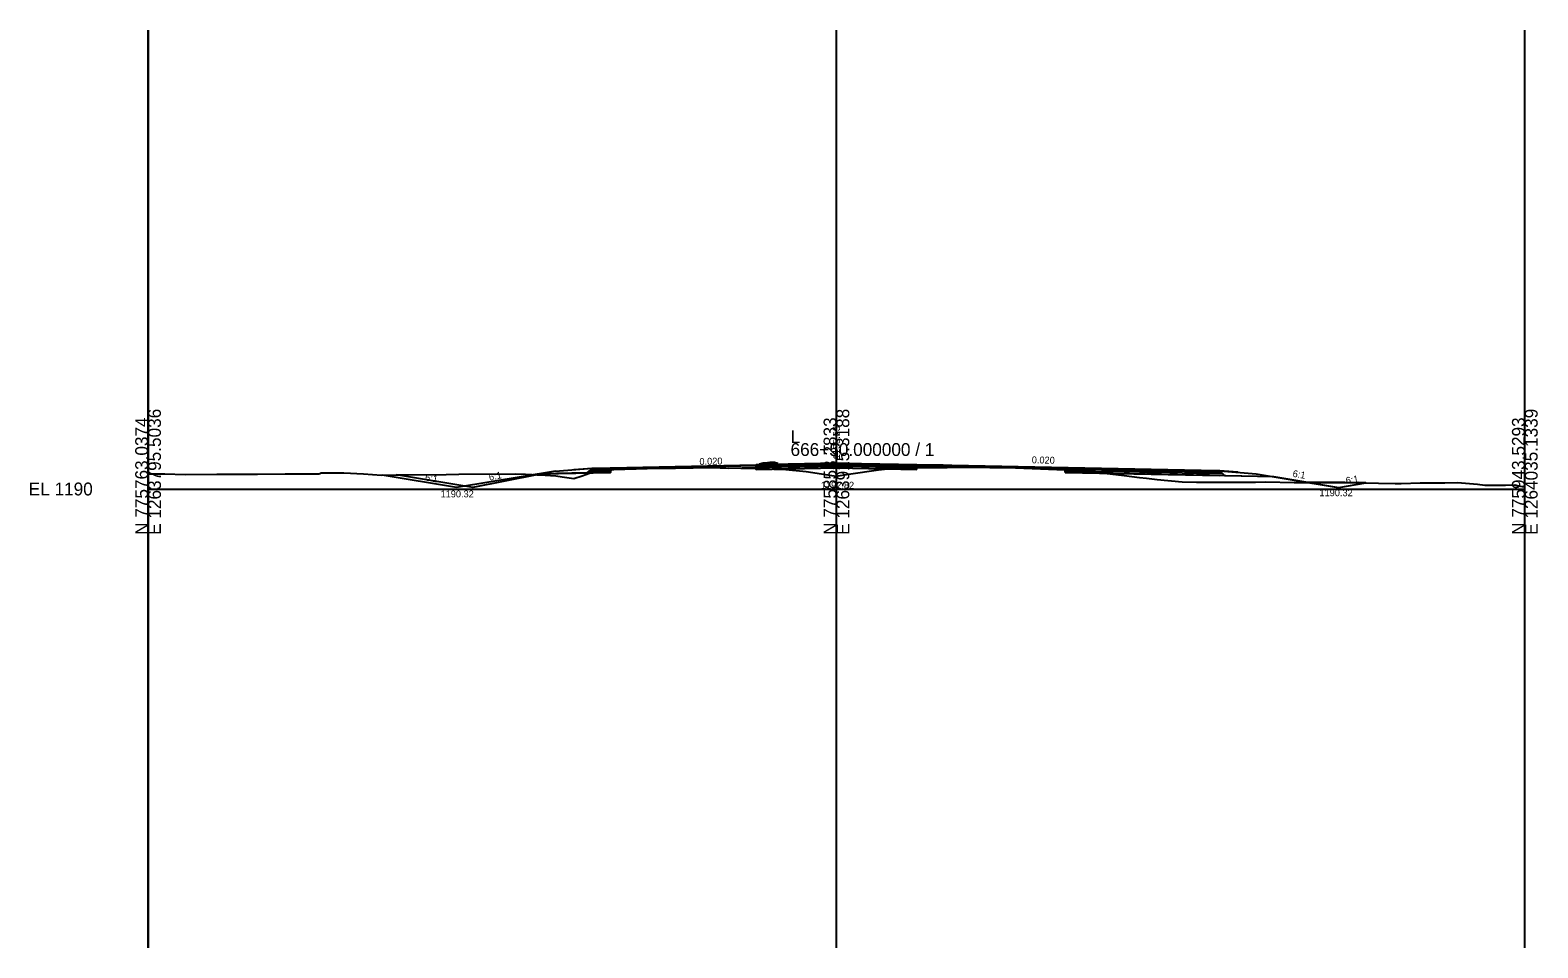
# Model space of a CAD drawing. Extents: x -41 to 1262860, y -100 to 777489.
# Drawn here: x -25.7 to 302.8, y 1805 to 2005 of the extents above; entities that cross this region are included whole.
import ezdxf

# ---------------------------------------------------------------- set-up
doc = ezdxf.new("R2010")
doc.units = 0
for name, color, linetype in [('Exist Cross Section Cell', 7, 'Continuous'), ('Exist XS Center Line Elevation Label', 7, 'Continuous'), ('Exist XS Ground Line', 7, 'Continuous'), ('Prop CMT Pvmt Course 1', 7, 'Continuous'), ('Prop CMT Pvmt Course 2', 7, 'Continuous'), ('Prop CMT Pvmt Course 4', 7, 'Continuous'), ('Prop CMT Pvmt Surface', 7, 'Continuous'), ('Prop CMT Shld Paved Course 1', 7, 'Continuous'), ('Prop CMT Shld Paved Course 2', 7, 'Continuous'), ('Prop CMT Shld Paved Course 4', 7, 'Continuous'), ('Prop CMT Subgrade Earthwork', 7, 'Continuous'), ('Prop Conc Curb and Gutter', 7, 'Continuous'), ('Prop Conc Island Cover', 7, 'Continuous'), ('Prop XS Ditch Standard Text', 7, 'Continuous'), ('Prop XS Earthwork Shape', 7, 'Continuous'), ('Prop XS Exc Vertical Line 1', 7, 'Continuous'), ('Prop XS Exc Vertical Line 2', 7, 'Continuous'), ('Prop XS Exc Vertical Line 3', 7, 'Continuous'), ('Prop XS Finish Grade', 7, 'Continuous'), ('Prop XS Hydro Elevations', 7, 'Continuous'), ('Prop XS SE Text', 7, 'Continuous'), ('Prop XS Side Slope Text', 7, 'Continuous'), ('Scratch_Level_4', 7, 'Continuous'), ('Scratch_Level_5', 7, 'Continuous'), ('Scratch_Level_6', 7, 'Continuous')]:
    doc.layers.add(name, color=color, linetype=linetype)

msp = doc.modelspace()

# ---------------------------------------------------------------- linework, layer by layer
at = {"layer": 'Exist Cross Section Cell'}
for p, q in [((150, 1905), (150, 1915)), ((0, 1905), (150, 1905)), ((150, 1905), (300, 1905))]:
    msp.add_line(p, q, dxfattribs=at)
at = {"layer": 'Exist XS Ground Line'}
msp.add_lwpolyline([(0, 1908.32), (3.62, 1908.27), (8.07, 1908.16), (14.98, 1908.25), (16.8, 1908.26), (23.82, 1908.26), (29.87, 1908.33), (37.24, 1908.31), (37.42, 1908.39), (37.74, 1908.54), (42.69, 1908.5), (46.95, 1908.32), (50.86, 1908.02), (54.64, 1908.12), (64.93, 1908.19), (67.7, 1908.24), (80.12, 1908.28), (82.21, 1908.24), (86.52, 1908.01), (88.89, 1907.85), (90.23, 1907.65), (92.78, 1907.3), (94.6, 1907.88), (96.18, 1908.47), (98, 1908.76), (99.23, 1908.96), (100.09, 1909.06), (101.49, 1909.24), (108.76, 1909.46), (110.72, 1909.52), (114.93, 1909.57), (122.69, 1909.66), (132.39, 1909.44), (135.4, 1909.37), (136.35, 1909.34), (139, 1909.27), (143.39, 1908.79), (145.8, 1908.42), (149.96, 1907.82), (152.65, 1908.23), (159.19, 1909.21), (161.1, 1909.42), (161.43, 1909.44), (164.51, 1909.58), (165.67, 1909.59), (176.58, 1909.75), (177.81, 1909.74), (188.99, 1909.59), (199.82, 1909.19), (201.18, 1909.14), (201.48, 1909.12), (204.78, 1908.94), (206.45, 1908.73), (212.71, 1907.91), (216.01, 1907.51), (217.55, 1907.35), (219.86, 1907.07), (225.33, 1906.54), (228.44, 1906.47), (232.88, 1906.51), (234.56, 1906.5), (241.28, 1906.5), (243.54, 1906.54), (249.75, 1906.45), (256.43, 1906.44), (260.81, 1906.39), (268.11, 1906.26), (271.76, 1906.19), (273.05, 1906.22), (277.23, 1906.32), (282.56, 1906.35), (285.34, 1906.45), (289.66, 1906.08), (291.26, 1905.87), (295.76, 1905.87), (297.84, 1905.9), (298.09, 1905.83), (298.63, 1905.72), (300, 1905.49)], dxfattribs=at)
at = {"layer": 'Prop CMT Pvmt Course 1'}
for points in [[(100.79, 1909.39), (100.79, 1909.64), (132.5, 1910.28), (132.5, 1910.28), (132.5, 1910.03), (132.5, 1910.03), (132.5, 1910.03), (100.79, 1909.39), (100.79, 1909.39)], [(229.45, 1908.79), (229.45, 1909.04), (175.13, 1910.12), (175.13, 1910.12), (174.75, 1910.13), (174.75, 1910.13), (174.1, 1910.14), (174.1, 1910.14), (173.25, 1910.16), (173.25, 1910.16), (172.3, 1910.18), (172.3, 1910.18), (171.37, 1910.2), (171.37, 1910.2), (170.58, 1910.21), (170.58, 1910.21), (170.02, 1910.23), (170.02, 1910.23), (167.5, 1910.28), (167.5, 1910.28), (167.5, 1910.03), (167.5, 1910.03), (167.5, 1910.03), (170.02, 1909.98), (170.02, 1909.98), (170.58, 1909.96), (170.58, 1909.96), (171.37, 1909.95), (171.37, 1909.95), (172.3, 1909.93), (172.3, 1909.93), (173.25, 1909.91), (173.25, 1909.91), (174.1, 1909.89), (174.1, 1909.89), (174.75, 1909.88), (174.75, 1909.88), (175.13, 1909.87), (175.13, 1909.87), (229.45, 1908.79), (229.45, 1908.79)]]:
    msp.add_lwpolyline(points, dxfattribs=at)
at = {"layer": 'Prop CMT Pvmt Course 2'}
msp.add_lwpolyline([(132.5, 1909.69), (138, 1909.8), (150, 1910.05), (150, 1910.05), (155.44, 1909.94), (155.44, 1909.94), (167.5, 1909.69), (167.5, 1909.69), (167.5, 1910.03), (155.44, 1910.27), (155.44, 1910.27), (150, 1910.38), (150, 1910.38), (138, 1910.14), (132.5, 1910.03)], dxfattribs=at)
at = {"layer": 'Prop CMT Pvmt Course 4'}
msp.add_line((132.5, 1909.69), (132.5, 1909.24), dxfattribs=at)
at = {"layer": 'Prop CMT Pvmt Surface'}
for p, q in [((96.78, 1909.56), (100.79, 1909.64)), ((100.79, 1909.64), (132.5, 1910.28)), ((132.5, 1910.28), (150, 1910.63)), ((150, 1910.63), (167.5, 1910.28)), ((167.5, 1910.28), (229.45, 1909.04)), ((229.45, 1909.04), (233.54, 1908.96))]:
    msp.add_line(p, q, dxfattribs=at)
at = {"layer": 'Prop CMT Shld Paved Course 1'}
msp.add_line((100.77, 1909.64), (100.79, 1909.64), dxfattribs=at)
for points in [[(100.79, 1909.64), (100.79, 1909.64), (100.79, 1909.39), (100.79, 1909.39), (100.79, 1909.39), (96.52, 1909.31), (96.78, 1909.56), (96.78, 1909.56), (100.77, 1909.64)], [(132.5, 1910.03), (132.5, 1910.03), (150, 1910.38), (150, 1910.38), (155.44, 1910.27), (155.44, 1910.27), (167.5, 1910.03), (167.5, 1910.03), (167.5, 1910.28), (155.44, 1910.52), (155.44, 1910.52), (150, 1910.63), (150, 1910.63), (132.5, 1910.28), (132.5, 1910.28)], [(233.54, 1908.96), (229.45, 1909.04), (229.45, 1908.79), (229.45, 1908.79), (233.79, 1908.7), (233.79, 1908.7), (233.79, 1908.7), (233.54, 1908.96), (233.54, 1908.96)]]:
    msp.add_lwpolyline(points, dxfattribs=at)
at = {"layer": 'Prop CMT Shld Paved Course 2'}
for p, q in [((101.49, 1909.41), (100.79, 1909.39)), ((100.79, 1909.39), (100.79, 1909.15)), ((100.79, 1909.15), (101.49, 1909.24)), ((100.79, 1909.15), (100.79, 1909.15)), ((108.76, 1909.55), (101.49, 1909.41)), ((101.49, 1909.24), (108.76, 1909.46)), ((101.49, 1909.41), (101.49, 1909.41)), ((101.49, 1909.41), (101.49, 1909.41)), ((101.49, 1909.24), (101.49, 1909.24)), ((101.49, 1909.24), (101.49, 1909.24)), ((110.72, 1909.59), (108.76, 1909.55)), ((108.76, 1909.55), (108.76, 1909.55)), ((108.76, 1909.46), (110.72, 1909.52)), ((108.76, 1909.46), (108.76, 1909.46)), ((114.93, 1909.67), (110.72, 1909.59)), ((110.72, 1909.52), (114.93, 1909.57)), ((122.69, 1909.83), (114.93, 1909.67)), ((114.93, 1909.67), (114.93, 1909.67)), ((114.93, 1909.57), (122.69, 1909.66)), ((114.93, 1909.57), (114.93, 1909.57)), ((132.39, 1910.02), (122.69, 1909.83)), ((122.69, 1909.83), (122.69, 1909.83)), ((122.69, 1909.83), (122.69, 1909.83)), ((122.69, 1909.66), (122.69, 1909.66)), ((122.69, 1909.66), (122.69, 1909.66)), ((122.69, 1909.66), (126.55, 1909.57)), ((126.55, 1909.57), (132.39, 1909.69)), ((126.55, 1909.57), (126.55, 1909.57)), ((132.5, 1910.03), (132.39, 1910.02)), ((132.39, 1910.02), (132.39, 1910.02)), ((132.39, 1909.69), (132.39, 1909.69)), ((132.39, 1909.69), (132.5, 1909.69)), ((132.5, 1909.69), (132.5, 1910.03)), ((132.5, 1909.69), (132.5, 1909.69))]:
    msp.add_line(p, q, dxfattribs=at)
for points in [[(100.79, 1909.39), (100.79, 1909.39), (100.79, 1909.06), (100.79, 1909.06), (100.79, 1909.06), (96.18, 1908.97), (96.52, 1909.31), (96.52, 1909.31), (100.77, 1909.39)], [(228.44, 1908.81), (225.33, 1908.87), (225.33, 1908.87), (219.86, 1908.98), (217.55, 1909.02), (217.55, 1909.02), (216.01, 1909.06), (212.71, 1909.12), (212.71, 1909.12), (206.45, 1909.25), (204.78, 1909.28), (204.78, 1909.28), (204.78, 1909.28), (201.48, 1909.35), (201.48, 1909.35), (201.18, 1909.35), (201.18, 1909.35), (201.18, 1909.35), (199.82, 1909.38), (199.82, 1909.38), (188.99, 1909.6), (177.81, 1909.82), (177.81, 1909.82), (176.58, 1909.84), (176.58, 1909.84), (175.13, 1909.87), (174.75, 1909.88), (174.75, 1909.88), (174.1, 1909.89), (174.1, 1909.89), (173.25, 1909.91), (173.25, 1909.91), (172.3, 1909.93), (172.3, 1909.93), (172.3, 1909.93), (171.37, 1909.95), (171.37, 1909.95), (170.58, 1909.96), (170.58, 1909.96), (170.02, 1909.98), (167.5, 1910.03), (167.5, 1910.03), (167.5, 1909.69), (167.5, 1909.69), (167.5, 1909.69), (167.5, 1909.69), (169.55, 1909.65), (169.55, 1909.65), (170.02, 1909.66), (170.58, 1909.67), (170.58, 1909.67), (171.37, 1909.68), (171.37, 1909.68), (172.3, 1909.69), (172.3, 1909.69), (172.3, 1909.69), (173.25, 1909.71), (173.25, 1909.71), (174.1, 1909.72), (174.1, 1909.72), (174.75, 1909.73), (174.75, 1909.73), (175.13, 1909.73), (176.58, 1909.75), (176.58, 1909.75), (177.81, 1909.74), (177.81, 1909.74), (188.99, 1909.59), (199.82, 1909.19), (199.82, 1909.19), (199.82, 1909.05), (206.45, 1908.91), (212.71, 1908.79), (212.71, 1908.79), (216.01, 1908.72), (217.55, 1908.69), (217.55, 1908.69), (219.86, 1908.65), (225.33, 1908.54), (225.33, 1908.54), (228.44, 1908.47), (228.44, 1908.47), (229.45, 1908.45), (229.45, 1908.45), (229.45, 1908.79), (228.44, 1908.81), (228.44, 1908.81)], [(233.79, 1908.7), (229.45, 1908.79), (229.45, 1908.45), (229.45, 1908.45), (234.13, 1908.36), (234.13, 1908.36), (234.13, 1908.36), (233.79, 1908.7), (233.79, 1908.7)]]:
    msp.add_lwpolyline(points, dxfattribs=at)
at = {"layer": 'Prop CMT Shld Paved Course 4'}
for p, q in [((132.39, 1909.44), (126.55, 1909.57)), ((132.39, 1909.44), (132.5, 1909.43)), ((132.5, 1909.24), (150, 1909.59)), ((150, 1909.59), (167.5, 1909.24)), ((167.5, 1909.24), (167.5, 1909.69)), ((169.55, 1909.65), (167.5, 1909.62)), ((199.82, 1909.05), (199.82, 1908.59)), ((199.82, 1908.59), (233.54, 1907.91)), ((234.13, 1908.36), (229.45, 1908.45)), ((229.45, 1908), (229.45, 1908.45)), ((234.13, 1908.36), (234.13, 1908.36)), ((234.13, 1908.36), (234.6, 1907.89))]:
    msp.add_line(p, q, dxfattribs=at)
msp.add_lwpolyline([(100.79, 1909.06), (100.79, 1909.06), (100.79, 1908.6), (100.79, 1908.6), (100.79, 1908.6), (95.71, 1908.5), (96.18, 1908.97), (96.18, 1908.97), (96.18, 1908.97), (96.18, 1908.97), (100.77, 1909.06)], dxfattribs=at)
at = {"layer": 'Prop CMT Subgrade Earthwork'}
for p, q in [((100.79, 1908.6), (100.79, 1909.15)), ((150, 1909.59), (132.5, 1909.24)), ((132.5, 1909.24), (132.5, 1909.43)), ((167.5, 1909.24), (150, 1909.59)), ((167.5, 1909.24), (167.5, 1909.62)), ((199.82, 1908.59), (199.82, 1909.19)), ((85.66, 1908.3), (100.79, 1908.6)), ((245.32, 1907.68), (199.82, 1908.59))]:
    msp.add_line(p, q, dxfattribs=at)
at = {"layer": 'Prop Conc Curb and Gutter'}
for p, q in [((133.25, 1910.29), (133.26, 1910.46)), ((133.25, 1910.29), (133.25, 1910.29)), ((133.25, 1910.29), (133.25, 1910.17)), ((135.01, 1910.29), (133.25, 1910.29)), ((133.25, 1910.29), (133.25, 1910.29)), ((133.25, 1910.17), (133.25, 1910.17)), ((133.25, 1910.17), (135.01, 1910.17)), ((133.26, 1910.46), (134.01, 1910.71)), ((133.26, 1910.46), (133.26, 1910.46)), ((134.01, 1910.71), (135.01, 1910.73)), ((134.01, 1910.71), (134.01, 1910.71)), ((135.01, 1910.73), (135.01, 1910.29)), ((135.01, 1910.17), (135.01, 1910.29)), ((135.01, 1910.29), (135.01, 1910.29)), ((135.01, 1910.17), (135.01, 1910.17)), ((135.01, 1910.17), (135.01, 1910.17)), ((136.49, 1910.79), (135.49, 1910.81)), ((135.49, 1910.81), (135.49, 1910.37)), ((137.25, 1910.37), (135.49, 1910.37)), ((135.49, 1910.37), (135.49, 1910.25)), ((135.49, 1910.37), (135.49, 1910.37)), ((135.49, 1910.25), (135.49, 1910.25)), ((135.49, 1910.25), (137.25, 1910.25)), ((137.24, 1910.54), (136.49, 1910.79)), ((136.49, 1910.79), (136.49, 1910.79)), ((137.25, 1910.37), (137.24, 1910.54)), ((137.24, 1910.54), (137.24, 1910.54)), ((137.25, 1910.25), (137.25, 1910.37)), ((137.25, 1910.37), (137.25, 1910.37)), ((137.25, 1910.37), (137.25, 1910.37)), ((137.25, 1910.25), (137.25, 1910.25)), ((137.25, 1910.25), (137.25, 1910.25))]:
    msp.add_line(p, q, dxfattribs=at)
at = {"layer": 'Prop Conc Island Cover'}
for p, q in [((135.49, 1910.81), (135.01, 1910.73)), ((135.01, 1910.73), (135.01, 1910.48)), ((135.49, 1910.55), (135.01, 1910.47)), ((135.49, 1910.56), (135.49, 1910.81)), ((135.49, 1910.81), (135.49, 1910.81)), ((135.49, 1910.56), (135.49, 1910.56))]:
    msp.add_line(p, q, dxfattribs=at)
at = {"layer": 'Prop XS Earthwork Shape'}
for points in [[(100.79, 1908.6), (100.79, 1909.15), (100.09, 1909.06), (99.23, 1908.96), (98, 1908.76), (96.44, 1908.51)], [(135.4, 1909.37), (136.35, 1909.34), (136.91, 1909.33), (132.5, 1909.24), (132.5, 1909.43)], [(159.19, 1909.21), (160.69, 1909.37), (150, 1909.59), (136.91, 1909.33), (139, 1909.27), (143.39, 1908.79), (145.8, 1908.42), (149.96, 1907.82), (152.65, 1908.23)], [(167.5, 1909.24), (167.5, 1909.62), (165.67, 1909.59), (164.51, 1909.58), (161.43, 1909.44), (161.1, 1909.42), (160.69, 1909.37)], [(199.82, 1908.59), (199.82, 1909.19), (201.18, 1909.14), (201.48, 1909.12), (204.78, 1908.94), (206.45, 1908.73), (208.96, 1908.41)], [(54.64, 1908.12), (64.93, 1908.19), (67.7, 1908.24), (80.12, 1908.28), (82.21, 1908.24), (84.7, 1908.11), (70.79, 1905.32), (54.11, 1908.1)], [(90.23, 1907.65), (92.78, 1907.3), (94.6, 1907.88), (96.18, 1908.47), (96.44, 1908.51), (95.71, 1908.5), (85.66, 1908.3), (84.7, 1908.11), (86.52, 1908.01), (88.89, 1907.85)], [(245.32, 1907.68), (234.6, 1907.89), (208.96, 1908.41), (212.71, 1907.91), (216.01, 1907.51), (217.55, 1907.35), (219.86, 1907.07), (225.33, 1906.54), (228.44, 1906.47), (232.88, 1906.51), (234.56, 1906.5), (241.28, 1906.5), (243.54, 1906.54), (249.75, 1906.45), (252.72, 1906.44)], [(259.45, 1905.32), (265.38, 1906.31), (260.81, 1906.39), (256.43, 1906.44), (252.72, 1906.44)]]:
    msp.add_lwpolyline(points, close=True, dxfattribs=at)
at = {"layer": 'Prop XS Exc Vertical Line 1'}
msp.add_line((0, 1805), (0, 2005), dxfattribs=at)
at = {"layer": 'Prop XS Exc Vertical Line 2'}
msp.add_line((150, 1805), (150, 2005), dxfattribs=at)
at = {"layer": 'Prop XS Exc Vertical Line 3'}
msp.add_line((300, 1805), (300, 2005), dxfattribs=at)
at = {"layer": 'Prop XS Finish Grade'}
for p, q in [((88.79, 1908.92), (67.19, 1905.32)), ((88.79, 1908.92), (96.77, 1909.56)), ((92.77, 1909.24), (96.78, 1909.56)), ((96.78, 1909.56), (95.71, 1908.5)), ((233.54, 1908.96), (241.45, 1908.32)), ((233.54, 1908.96), (234.6, 1907.89)), ((67.19, 1905.32), (51, 1908.02)), ((241.45, 1908.32), (259.45, 1905.32)), ((259.45, 1905.32), (265.38, 1906.31))]:
    msp.add_line(p, q, dxfattribs=at)
for points in [[(92.77, 1909.24), (96.77, 1909.56), (96.77, 1909.56)], [(237.45, 1908.64), (237.45, 1908.64), (233.54, 1908.96)]]:
    msp.add_lwpolyline(points, dxfattribs=at)
at = {"layer": 'Scratch_Level_4'}
msp.add_line((300, 1805), (300, 2005), dxfattribs=at)
at = {"layer": 'Scratch_Level_5'}
for p, q in [((150, 1906), (150, 1927.88)), ((241.45, 1908.32), (259.34, 1905.34))]:
    msp.add_line(p, q, dxfattribs=at)
at = {"layer": 'Scratch_Level_6'}
msp.add_line((0, 2005), (0, 1805), dxfattribs=at)

# ---------------------------------------------------------------- texts
at = {"layer": 'Exist Cross Section Cell'}
for s, p in [('E 1263795.5036', (2.8, 1895)), ('E 1263915.3188', (152.8, 1895)), ('E 1264035.1339', (302.8, 1895)), ('N 775763.0374', (0, 1895)), ('N 775853.2833', (150, 1895)), ('N 775943.5293', (300, 1895))]:
    msp.add_text(s, height=2.8, rotation=90, dxfattribs=at).set_placement(p)
for s, p in [('L', (140, 1915)), ('666+50.000000 / 1', (140, 1912.2)), ('EL 1190', (-26, 1903.6))]:
    msp.add_text(s, height=2.8, dxfattribs=at).set_placement(p)
at = {"layer": 'Exist XS Center Line Elevation Label'}
msp.add_text('1192.82', height=1.5, dxfattribs=at).set_placement((146.61, 1905.07))
at = {"layer": 'Prop XS Ditch Standard Text'}
for p in [(63.73, 1903.18), (255.25, 1903.43)]:
    msp.add_text('1190.32', height=1.5, dxfattribs=at).set_placement(p)
at = {"layer": 'Prop XS Hydro Elevations'}
msp.add_text('1195.63', height=1.5, rotation=90, dxfattribs=at).set_placement((150.75, 1911.47))
at = {"layer": 'Prop XS SE Text'}
for rotation, p in [(358.8542, (192.55, 1910.61)), (1.1458, (120.16, 1910.25))]:
    msp.add_text('0.020', height=1.5, rotation=rotation, dxfattribs=at).set_placement(p)
at = {"layer": 'Prop XS Side Slope Text'}
for rotation, p in [(350.5377, (249.33, 1907.67)), (350.5191, (60.27, 1906.86)), (11.3099, (74.42, 1906.81)), (9.4809, (261.11, 1906.06))]:
    msp.add_text('6:1', height=1.5, rotation=rotation, dxfattribs=at).set_placement(p)

doc.saveas('drawing.dxf')
